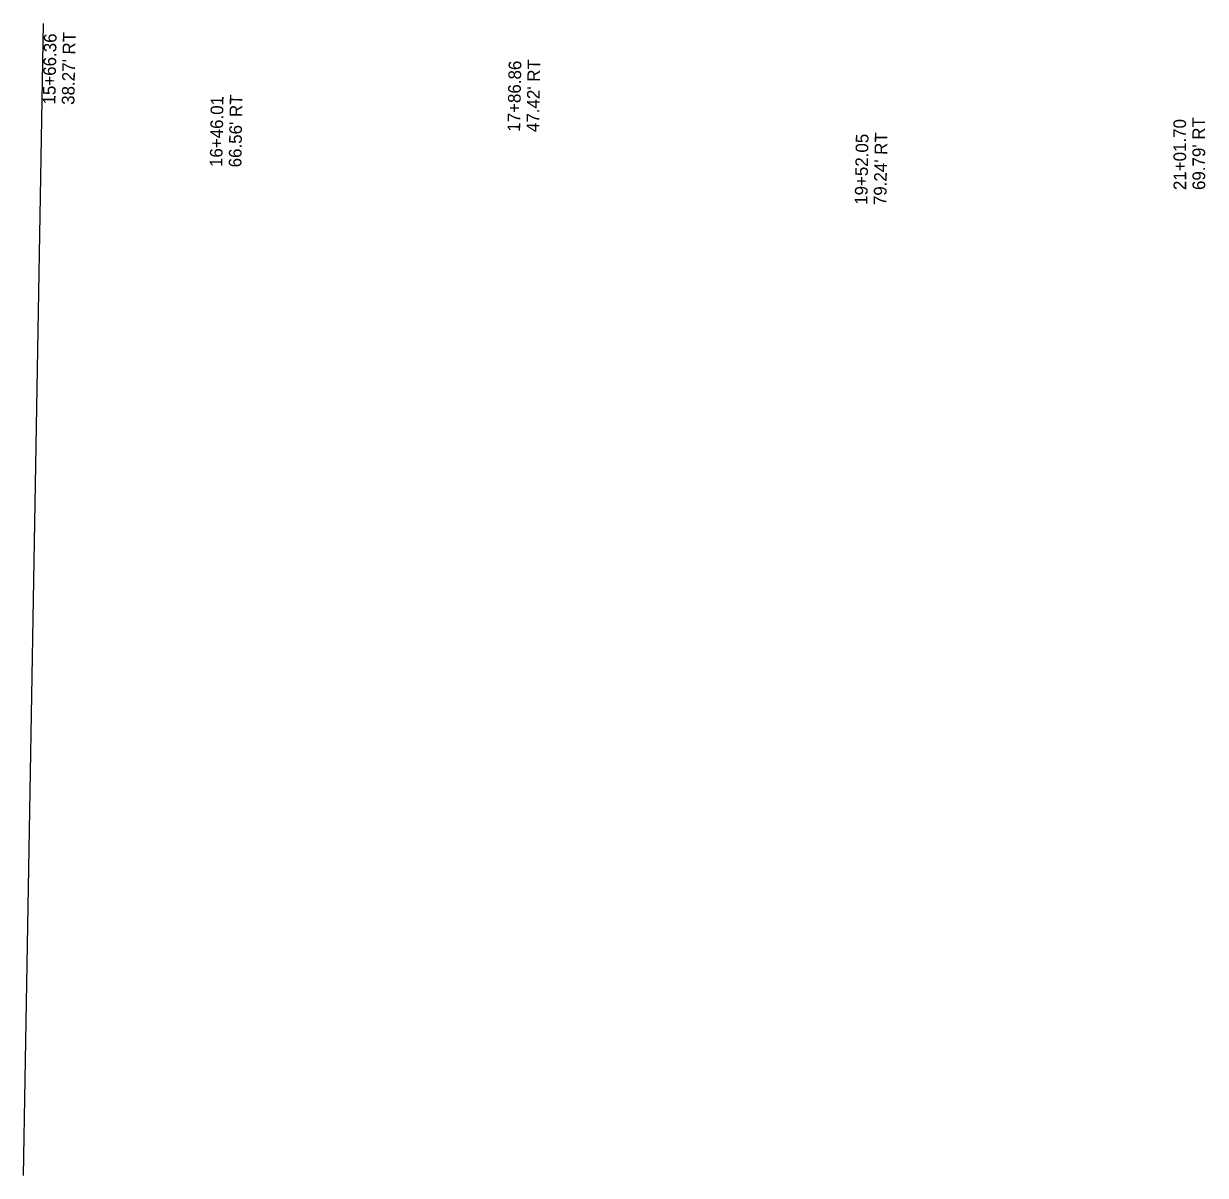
# Model space of a CAD drawing. Extents: x 653223 to 654433, y 407923 to 411694.
import ezdxf

# ---------------------------------------------------------------- set-up
doc = ezdxf.new("R2010")
doc.units = 0
doc.layers.add('H_Headwall', color=7, linetype='Continuous')

msp = doc.modelspace()

# ---------------------------------------------------------------- linework, layer by layer
at = {"layer": 'H_Headwall'}
msp.add_line((653222.75, 407923.47), (653232.09, 408469.44), dxfattribs=at)

# ---------------------------------------------------------------- texts
for s, rotation, p in [('15+66.36 ', 89.0197, (653237.8, 408431.06)), ("38.27' RT  ", 89.0197, (653246.8, 408430.91)), ("47.42' RT  ", 89.0197, (653467.11, 408417.99)), ('17+86.86 ', 89.0197, (653458.11, 408418.15)), ("66.56' RT  ", 89.0197, (653325.95, 408401.27)), ('16+46.01 ', 89.0197, (653316.95, 408401.42)), ('21+01.70 ', 90.1496, (653773.9, 408390.54)), ("69.79' RT  ", 90.1496, (653782.9, 408390.57)), ('19+52.05 ', 89.0197, (653622.73, 408383.5)), ("79.24' RT  ", 89.0197, (653631.73, 408383.35))]:
    msp.add_text(s, height=6, rotation=rotation, dxfattribs=at).set_placement(p)

doc.saveas('drawing.dxf')
